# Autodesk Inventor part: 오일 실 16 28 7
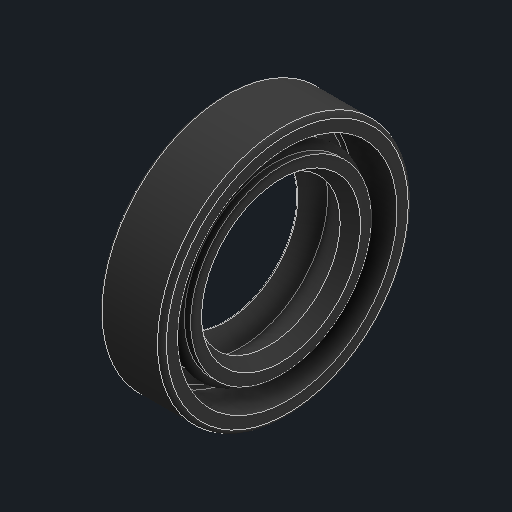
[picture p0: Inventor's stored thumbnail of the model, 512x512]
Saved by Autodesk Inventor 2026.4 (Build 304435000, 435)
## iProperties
Created: 2026-09
Part Number: 오일 실 16 28 7
Material: 고무
Description: 오일-실
Document SubType Name: Modeling
Designer: user
Density: 0.93 g/cm^3
Appearance: 기본값
Author: jhkim
Sending System: Autodesk Inventor 2027
Preprocessor: ST-DEVELOPER v20.1
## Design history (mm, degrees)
feature "Solid1"
node "솔리드1"
